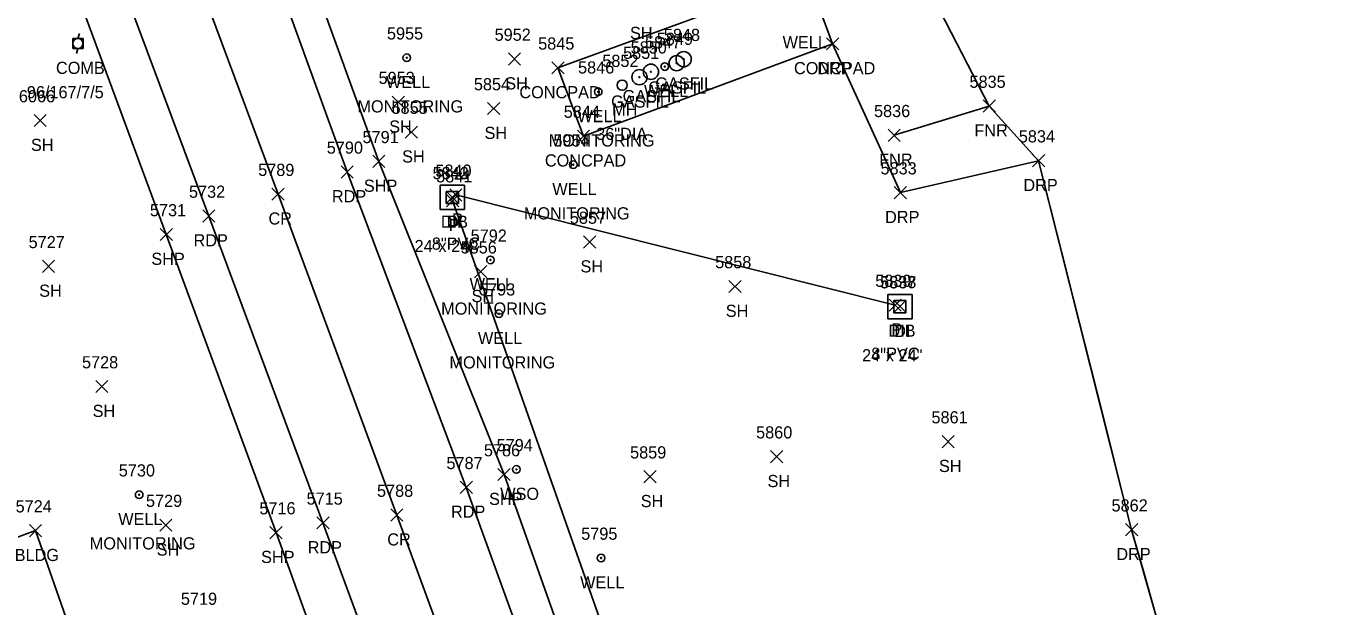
# Model space of a CAD drawing. Extents: x 1769141 to 1770911, y 735471 to 741449.
# Drawn here: x 1770371.3 to 1770586.8, y 740179.7 to 740275.1 of the extents above; entities that cross this region are included whole.
import ezdxf

# ---------------------------------------------------------------- set-up
doc = ezdxf.new("R2010")
doc.units = 0
for name, color, linetype in [('D_A', 7, 'Continuous'), ('D_C', 7, 'Continuous'), ('D_I', 7, 'Continuous'), ('D_TIC', 7, 'Continuous'), ('DCP', 7, 'Continuous'), ('DS', 7, 'Continuous'), ('L_A', 7, 'Continuous'), ('L_I', 7, 'Continuous'), ('L_TIC', 7, 'Continuous'), ('LBC', 7, 'Continuous'), ('LFNC', 7, 'Continuous'), ('LS', 7, 'Continuous'), ('LSOGP', 7, 'Continuous'), ('P_A', 7, 'Continuous'), ('P_I', 7, 'Continuous'), ('P_TIC', 7, 'Continuous'), ('PET', 7, 'Continuous'), ('PRC', 7, 'Continuous'), ('PSP', 7, 'Continuous'), ('R_A', 7, 'Continuous'), ('R_I', 7, 'Continuous'), ('R_TIC', 7, 'Continuous'), ('RDP', 7, 'Continuous'), ('U_A', 7, 'Continuous'), ('U_C', 7, 'Continuous'), ('U_I', 7, 'Continuous'), ('UMFC', 7, 'Continuous'), ('UP', 7, 'Continuous'), ('UUMH', 7, 'Continuous'), ('UWV', 7, 'Continuous'), ('UWW', 7, 'Continuous')]:
    doc.layers.add(name, color=color, linetype=linetype)

msp = doc.modelspace()

# ---------------------------------------------------------------- linework, layer by layer
at = {"layer": 'D_TIC'}
for points in [[(1770440.39, 740245.99), (1770442.39, 740247.99)], [(1770442.39, 740245.99), (1770440.39, 740247.99)], [(1770440.94, 740246.38), (1770442.94, 740248.38)], [(1770442.94, 740246.38), (1770440.94, 740248.38)], [(1770440.42, 740245.45), (1770442.42, 740247.45)], [(1770442.42, 740245.45), (1770440.42, 740247.45)], [(1770513.2, 740228.27), (1770515.2, 740230.27)], [(1770515.2, 740228.27), (1770513.2, 740230.27)], [(1770513.99, 740228.06), (1770515.99, 740230.06)], [(1770515.99, 740228.06), (1770513.99, 740230.06)]]:
    msp.add_lwpolyline(points, dxfattribs=at)
at = {"layer": 'DCP'}
for points in [[(1770586.82, 739833.24), (1770441.42, 740246.45)], [(1770514.2, 740229.27), (1770441.94, 740247.38)]]:
    msp.add_lwpolyline(points, dxfattribs=at)
at = {"layer": 'DS'}
for p, q in [((1770439.38, 740248.97), (1770443.38, 740248.97)), ((1770439.38, 740244.97), (1770439.38, 740248.97)), ((1770440.38, 740245.97), (1770440.38, 740247.97)), ((1770440.38, 740247.97), (1770442.38, 740247.97)), ((1770442.38, 740247.97), (1770442.38, 740245.97)), ((1770443.38, 740248.97), (1770443.38, 740244.97)), ((1770442.38, 740245.97), (1770440.38, 740245.97)), ((1770441.39, 740246.98), (1770441.39, 740246.98)), ((1770441.39, 740246.98), (1770441.39, 740246.98)), ((1770443.38, 740244.97), (1770439.38, 740244.97)), ((1770512.98, 740231.02), (1770516.98, 740231.02)), ((1770512.98, 740227.02), (1770512.98, 740231.02)), ((1770516.98, 740231.02), (1770516.98, 740227.02)), ((1770513.98, 740228.02), (1770513.98, 740230.02)), ((1770513.98, 740230.02), (1770515.98, 740230.02)), ((1770514.98, 740229.02), (1770514.98, 740229.02)), ((1770514.98, 740229.02), (1770514.98, 740229.02)), ((1770515.98, 740230.02), (1770515.98, 740228.02)), ((1770516.98, 740227.02), (1770512.98, 740227.02)), ((1770515.98, 740228.02), (1770513.98, 740228.02))]:
    msp.add_line(p, q, dxfattribs=at)
at = {"layer": 'L_TIC'}
for points in [[(1770502.91, 740271.24), (1770504.91, 740273.24)], [(1770504.91, 740271.24), (1770502.91, 740273.24)], [(1770450.59, 740268.74), (1770452.59, 740270.74)], [(1770452.59, 740268.74), (1770450.59, 740270.74)], [(1770457.75, 740267.28), (1770459.75, 740269.28)], [(1770459.75, 740267.28), (1770457.75, 740269.28)], [(1770431.51, 740261.63), (1770433.51, 740263.63)], [(1770433.51, 740261.63), (1770431.51, 740263.63)], [(1770528.68, 740261), (1770530.68, 740263)], [(1770530.68, 740261), (1770528.68, 740263)], [(1770447.18, 740260.59), (1770449.18, 740262.59)], [(1770449.18, 740260.59), (1770447.18, 740262.59)], [(1770372.59, 740258.62), (1770374.59, 740260.62)], [(1770374.59, 740258.62), (1770372.59, 740260.62)], [(1770433.64, 740256.72), (1770435.64, 740258.72)], [(1770435.64, 740256.72), (1770433.64, 740258.72)], [(1770461.96, 740256.06), (1770463.96, 740258.06)], [(1770463.96, 740256.06), (1770461.96, 740258.06)], [(1770513.03, 740256.19), (1770515.03, 740258.19)], [(1770515.03, 740256.19), (1770513.03, 740258.19)], [(1770462.96, 740238.64), (1770464.96, 740240.64)], [(1770464.96, 740238.64), (1770462.96, 740240.64)], [(1770373.96, 740234.64), (1770375.96, 740236.64)], [(1770375.96, 740234.64), (1770373.96, 740236.64)], [(1770445.05, 740233.76), (1770447.05, 740235.76)], [(1770447.05, 740233.76), (1770445.05, 740235.76)], [(1770486.86, 740231.33), (1770488.86, 740233.33)], [(1770488.86, 740231.33), (1770486.86, 740233.33)], [(1770382.74, 740214.87), (1770384.74, 740216.87)], [(1770384.74, 740214.87), (1770382.74, 740216.87)], [(1770521.91, 740205.82), (1770523.91, 740207.82)], [(1770523.91, 740205.82), (1770521.91, 740207.82)], [(1770493.72, 740203.34), (1770495.72, 740205.34)], [(1770495.72, 740203.34), (1770493.72, 740205.34)], [(1770472.87, 740200.05), (1770474.87, 740202.05)], [(1770474.87, 740200.05), (1770472.87, 740202.05)], [(1770393.27, 740192.08), (1770395.27, 740194.08)], [(1770395.27, 740192.08), (1770393.27, 740194.08)], [(1770371.82, 740191.18), (1770373.82, 740193.18)], [(1770373.82, 740191.18), (1770371.82, 740193.18)]]:
    msp.add_lwpolyline(points, dxfattribs=at)
at = {"layer": 'LBC'}
msp.add_lwpolyline([(1770378.82, 740119.65), (1770395.86, 740125.83), (1770391, 740140.49), (1770390.29, 740142.39), (1770372.82, 740192.18), (1770367.05, 740190.05), (1770354, 740228.14)], dxfattribs=at)
at = {"layer": 'LFNC'}
msp.add_lwpolyline([(1770529.68, 740262), (1770514.03, 740257.19)], dxfattribs=at)
at = {"layer": 'LS'}
for points in [[(1770499.82, 740283.3), (1770503.91, 740272.24), (1770462.96, 740257.06), (1770458.75, 740268.28)], [(1770458.75, 740268.28), (1770499.82, 740283.3)]]:
    msp.add_lwpolyline(points, dxfattribs=at)
at = {"layer": 'LSOGP'}
msp.add_lwpolyline([(1770556.97, 740178.68), (1770555.03, 740185.51), (1770553.09, 740192.33), (1770551.17, 740199.91), (1770549.26, 740207.5), (1770547.35, 740215.09), (1770545.44, 740222.67), (1770543.53, 740230.26), (1770541.61, 740237.85), (1770539.7, 740245.43), (1770537.79, 740253.02), (1770529.68, 740262), (1770513.53, 740293.28)], dxfattribs=at)
at = {"layer": 'P_TIC'}
for points in [[(1770423.08, 740250.17), (1770425.08, 740252.17)], [(1770425.08, 740250.17), (1770423.08, 740252.17)], [(1770428.3, 740251.9), (1770430.3, 740253.9)], [(1770430.3, 740251.9), (1770428.3, 740253.9)], [(1770411.72, 740246.51), (1770413.72, 740248.51)], [(1770413.72, 740246.51), (1770411.72, 740248.51)], [(1770400.33, 740242.92), (1770402.33, 740244.92)], [(1770402.33, 740242.92), (1770400.33, 740244.92)], [(1770393.34, 740239.88), (1770395.34, 740241.88)], [(1770395.34, 740239.88), (1770393.34, 740241.88)], [(1770448.88, 740200.4), (1770450.88, 740202.4)], [(1770450.88, 740200.4), (1770448.88, 740202.4)], [(1770442.67, 740198.3), (1770444.67, 740200.3)], [(1770444.67, 740198.3), (1770442.67, 740200.3)], [(1770419.1, 740192.45), (1770421.1, 740194.45)], [(1770421.1, 740192.45), (1770419.1, 740194.45)], [(1770431.25, 740193.74), (1770433.25, 740195.74)], [(1770433.25, 740193.74), (1770431.25, 740195.74)], [(1770411.39, 740190.86), (1770413.39, 740192.86)], [(1770413.39, 740190.86), (1770411.39, 740192.86)]]:
    msp.add_lwpolyline(points, dxfattribs=at)
at = {"layer": 'PET'}
for points in [[(1770553.27, 739901.7), (1770537.83, 739943.38), (1770523.77, 739980.77), (1770499.87, 740045.65), (1770491.21, 740069), (1770475.98, 740110.18), (1770458, 740159.65), (1770443.67, 740199.3), (1770424.08, 740251.17), (1770412.7, 740282.67), (1770395.6, 740328.61), (1770379.16, 740373.29), (1770360.22, 740424.51)], [(1770526.99, 739903.96), (1770508.61, 739952.73), (1770482.98, 740021.56), (1770465.73, 740068.87), (1770446.91, 740120.21), (1770436.39, 740149.2), (1770420.1, 740193.45), (1770401.33, 740243.92), (1770375.13, 740314.06), (1770354.08, 740371.38), (1770337.26, 740416.85)]]:
    msp.add_lwpolyline(points, dxfattribs=at)
at = {"layer": 'PRC'}
msp.add_lwpolyline([(1770544.53, 739890.8), (1770526.88, 739938.69), (1770512.58, 739976.28), (1770488.64, 740041.4), (1770480.72, 740062.92), (1770464.76, 740106.43), (1770446.69, 740155.46), (1770432.25, 740194.74), (1770412.72, 740247.51), (1770400.4, 740280.65), (1770384.57, 740323.92), (1770366.94, 740369.74), (1770348.35, 740420.63)], dxfattribs=at)
at = {"layer": 'PSP'}
for points in [[(1770540.34, 739951.65), (1770528.66, 739983.22), (1770504.99, 740047.85), (1770496.22, 740070.8), (1770481.82, 740111.56), (1770464.17, 740161.25), (1770449.88, 740201.4), (1770429.3, 740252.9), (1770418.04, 740283.83), (1770400.74, 740330.55), (1770384.34, 740374.74), (1770365.93, 740426.73), (1770363, 740434.14), (1770343.37, 740484.07), (1770326.57, 740533.85), (1770310.21, 740576.26), (1770285.85, 740639.32), (1770267.25, 740691.65), (1770245.28, 740742.42), (1770222.4, 740793.58), (1770203.84, 740840.26), (1770179.15, 740903.22)], [(1770519.72, 739902.09), (1770501.8, 739950.34), (1770476.26, 740018.87), (1770458.57, 740065.96), (1770452.77, 740080.17), (1770447.86, 740094.08), (1770439.07, 740117.75), (1770428.15, 740148.24), (1770412.39, 740191.86), (1770394.34, 740240.88), (1770368.09, 740312), (1770346.98, 740368.28), (1770329.75, 740414.99)]]:
    msp.add_lwpolyline(points, dxfattribs=at)
at = {"layer": 'R_TIC'}
for points in [[(1770502.91, 740271.24), (1770504.91, 740273.24)], [(1770504.91, 740271.24), (1770502.91, 740273.24)], [(1770536.79, 740252.02), (1770538.79, 740254.02)], [(1770538.79, 740252.02), (1770536.79, 740254.02)], [(1770514.05, 740246.76), (1770516.05, 740248.76)], [(1770516.05, 740246.76), (1770514.05, 740248.76)], [(1770552.09, 740191.33), (1770554.09, 740193.33)], [(1770554.09, 740191.33), (1770552.09, 740193.33)]]:
    msp.add_lwpolyline(points, dxfattribs=at)
at = {"layer": 'RDP'}
msp.add_lwpolyline([(1770503.91, 740272.24), (1770515.05, 740247.76), (1770537.79, 740253.02), (1770553.09, 740192.33), (1770560.85, 740165.04), (1770564.43, 740147.54)], dxfattribs=at)
at = {"layer": 'UMFC'}
for p, q in [((1770479.42, 740269.7), (1770479.42, 740269.7)), ((1770474.04, 740267.64), (1770474.04, 740267.64)), ((1770478.27, 740269.06), (1770478.27, 740269.06)), ((1770472.15, 740266.75), (1770472.15, 740266.75))]:
    msp.add_line(p, q, dxfattribs=at)
for centre, radius in [((1770478.27, 740269.06), 1.25), ((1770479.42, 740269.7), 1.25), ((1770479.42, 740269.7), 0.0833), ((1770472.15, 740266.75), 1.25), ((1770474.04, 740267.64), 1.25), ((1770474.04, 740267.64), 0.0833), ((1770478.27, 740269.06), 0.0833), ((1770472.15, 740266.75), 0.0833)]:
    msp.add_circle(centre, radius, dxfattribs=at)
at = {"layer": 'UP'}
for p, q in [((1770380.06, 740273.95), (1770379.81, 740273.12)), ((1770378.98, 740271.45), (1770378.98, 740273.12)), ((1770378.98, 740273.12), (1770380.65, 740273.12)), ((1770379.81, 740272.28), (1770379.81, 740272.28)), ((1770380.65, 740273.12), (1770380.65, 740271.45)), ((1770380.65, 740271.45), (1770378.98, 740271.45)), ((1770379.56, 740270.62), (1770379.81, 740271.45))]:
    msp.add_line(p, q, dxfattribs=at)
msp.add_circle((1770379.81, 740272.28), 0.833, dxfattribs=at)
at = {"layer": 'UUMH'}
for p, q in [((1770469.3, 740265.43), (1770469.3, 740265.43)), ((1770470.13, 740265.43), (1770470.13, 740265.43))]:
    msp.add_line(p, q, dxfattribs=at)
msp.add_circle((1770469.3, 740265.43), 0.833, dxfattribs=at)
at = {"layer": 'UWV'}
for radius in [0.625, 0.0833]:
    msp.add_circle((1770451.92, 740202.24), radius, dxfattribs=at)
at = {"layer": 'UWW'}
for centre, radius in [((1770433.89, 740269.95), 0.625), ((1770433.89, 740269.95), 0.0833), ((1770476.32, 740268.49), 0.625), ((1770476.32, 740268.49), 0.0833), ((1770465.36, 740264.35), 0.625), ((1770465.36, 740264.35), 0.0833), ((1770461.26, 740252.36), 0.625), ((1770461.26, 740252.36), 0.0833), ((1770447.65, 740236.7), 0.625), ((1770447.65, 740236.7), 0.0833), ((1770449.03, 740227.85), 0.625), ((1770449.03, 740227.85), 0.0833), ((1770389.88, 740198.09), 0.625), ((1770389.88, 740198.09), 0.0833), ((1770465.83, 740187.68), 0.625), ((1770465.83, 740187.68), 0.0833)]:
    msp.add_circle(centre, radius, dxfattribs=at)

# ---------------------------------------------------------------- texts
at = {"layer": 'D_A'}
for s, p in [('DIB', (1770439.49, 740241.99)), ('DI', (1770440.45, 740241.98)), ('P', (1770441.32, 740242.38)), ('P', (1770440.8, 740241.45)), ('P', (1770513.58, 740224.27)), ('DIB', (1770513.09, 740224.06)), ('DI', (1770514.04, 740224.02))]:
    msp.add_text(s, height=2, dxfattribs=at).set_placement(p)
at = {"layer": 'D_C'}
for s, p in [('24"x 24"', (1770435.17, 740237.98)), ('8"PVC', (1770438.01, 740238.38)), ('24"x 24"', (1770508.76, 740220.02)), ('8"PVC', (1770510.27, 740220.27))]:
    msp.add_text(s, height=2, dxfattribs=at).set_placement(p)
at = {"layer": 'D_I'}
for s, p in [('5840', (1770438.59, 740250.38)), ('5842', (1770438.13, 740249.99)), ('5843', (1770438.13, 740249.98)), ('5841', (1770438.72, 740249.45)), ('5839', (1770510.93, 740232.27)), ('5837', (1770511.72, 740232.02)), ('5838', (1770511.73, 740232.06))]:
    msp.add_text(s, height=2, dxfattribs=at).set_placement(p)
at = {"layer": 'L_A'}
for s, p in [('SH', (1770470.59, 740273.02)), ('CONCPAD', (1770497.56, 740267.24)), ('SH', (1770450.08, 740264.74)), ('CONCPAD', (1770452.4, 740263.28)), ('SH', (1770431, 740257.63)), ('SH', (1770446.67, 740256.59)), ('FNR', (1770527.22, 740257)), ('SH', (1770372.08, 740254.62)), ('SH', (1770433.12, 740252.72)), ('CONCPAD', (1770456.6, 740252.06)), ('FNR', (1770511.57, 740252.19)), ('SH', (1770462.45, 740234.64)), ('SH', (1770373.44, 740230.64)), ('SH', (1770444.54, 740229.76)), ('SH', (1770486.34, 740227.33)), ('SH', (1770382.23, 740210.87)), ('SH', (1770521.4, 740201.82)), ('SH', (1770493.21, 740199.34)), ('SH', (1770472.36, 740196.05)), ('SH', (1770392.76, 740188.08)), ('BLDG', (1770369.41, 740187.18))]:
    msp.add_text(s, height=2, dxfattribs=at).set_placement(p)
at = {"layer": 'L_I'}
for s, p in [('5952', (1770448.33, 740272.74)), ('5845', (1770455.49, 740271.28)), ('5953', (1770429.25, 740265.63)), ('5854', (1770444.92, 740264.59)), ('5835', (1770526.42, 740265)), ('6066', (1770370.1, 740262.62)), ('5855', (1770431.38, 740260.72)), ('5844', (1770459.7, 740260.06)), ('5836', (1770510.72, 740260.19)), ('5857', (1770460.7, 740242.64)), ('5727', (1770371.7, 740238.64)), ('5856', (1770442.74, 740237.76)), ('5858', (1770484.6, 740235.33)), ('5728', (1770380.48, 740218.87)), ('5861', (1770520.17, 740209.82)), ('5860', (1770491.33, 740207.34)), ('5859', (1770470.61, 740204.05)), ('5724', (1770369.56, 740195.18)), ('5729', (1770391, 740196.08)), ('5719', (1770396.74, 740179.98))]:
    msp.add_text(s, height=2, dxfattribs=at).set_placement(p)
at = {"layer": 'P_A'}
for s, p in [('RDP', (1770421.57, 740246.17)), ('SHP', (1770426.83, 740247.9)), ('CR', (1770411.15, 740242.51)), ('RDP', (1770398.82, 740238.92)), ('SHP', (1770391.88, 740235.88)), ('SHP', (1770447.42, 740196.4)), ('RDP', (1770441.16, 740194.3)), ('CR', (1770430.68, 740189.74)), ('RDP', (1770417.59, 740188.45)), ('SHP', (1770409.93, 740186.86))]:
    msp.add_text(s, height=2, dxfattribs=at).set_placement(p)
at = {"layer": 'P_I'}
for s, p in [('5791', (1770426.61, 740255.9)), ('5790', (1770420.73, 740254.17)), ('5789', (1770409.45, 740250.51)), ('5732', (1770398.07, 740246.92)), ('5731', (1770391.65, 740243.88)), ('5786', (1770446.57, 740204.4)), ('5787', (1770440.41, 740202.3)), ('5715', (1770417.41, 740196.45)), ('5788', (1770428.99, 740197.74)), ('5716', (1770409.65, 740194.86))]:
    msp.add_text(s, height=2, dxfattribs=at).set_placement(p)
at = {"layer": 'R_A'}
for p in [(1770501.4, 740267.24), (1770535.28, 740248.02), (1770512.54, 740242.76), (1770550.57, 740187.33)]:
    msp.add_text('DRP', height=2, dxfattribs=at).set_placement(p)
at = {"layer": 'R_I'}
for s, p in [('5834', (1770534.53, 740256.02)), ('5833', (1770511.79, 740250.76)), ('5862', (1770549.78, 740195.33))]:
    msp.add_text(s, height=2, dxfattribs=at).set_placement(p)
at = {"layer": 'U_A'}
for s, p in [('WELL', (1770495.69, 740271.5)), ('COMB', (1770376.2, 740267.28)), ('WELL', (1770430.46, 740264.95)), ('WELL', (1770472.89, 740263.49)), ('GASFIL', (1770473.61, 740264.06)), ('GASFIL', (1770474.76, 740264.7)), ('GASFIL', (1770467.49, 740261.75)), ('GASFIL', (1770469.38, 740262.64)), ('WELL', (1770461.93, 740259.35)), ('MH', (1770467.66, 740260.43)), ('WELL', (1770457.82, 740247.36)), ('WELL', (1770444.22, 740231.7)), ('WELL', (1770445.59, 740222.85)), ('WSO', (1770449.25, 740197.24)), ('WELL', (1770386.44, 740193.09)), ('WELL', (1770462.39, 740182.68))]:
    msp.add_text(s, height=2, dxfattribs=at).set_placement(p)
at = {"layer": 'U_C'}
for s, p in [('96/167/7/5', (1770371.41, 740263.28)), ('MONITORING', (1770425.77, 740260.95)), ('MONITORING', (1770457.24, 740255.35)), ('36"DIA', (1770465.04, 740256.43)), ('MONITORING', (1770453.14, 740243.36)), ('MONITORING', (1770439.54, 740227.7)), ('MONITORING', (1770440.91, 740218.85)), ('MONITORING', (1770381.76, 740189.09))]:
    msp.add_text(s, height=2, dxfattribs=at).set_placement(p)
at = {"layer": 'U_I'}
for s, p in [('5955', (1770430.63, 740272.95)), ('5849', (1770475, 740272.06)), ('5848', (1770476.16, 740272.7)), ('5851', (1770469.46, 740269.75)), ('5850', (1770470.7, 740270.64)), ('5847', (1770473.06, 740271.49)), ('5846', (1770462.05, 740267.35)), ('5852', (1770466.04, 740268.43)), ('5954', (1770458, 740255.36)), ('5792', (1770444.39, 740239.7)), ('5793', (1770445.77, 740230.85)), ('5794', (1770448.66, 740205.24)), ('5730', (1770386.53, 740201.09)), ('5795', (1770462.57, 740190.68))]:
    msp.add_text(s, height=2, dxfattribs=at).set_placement(p)

doc.saveas('drawing.dxf')
